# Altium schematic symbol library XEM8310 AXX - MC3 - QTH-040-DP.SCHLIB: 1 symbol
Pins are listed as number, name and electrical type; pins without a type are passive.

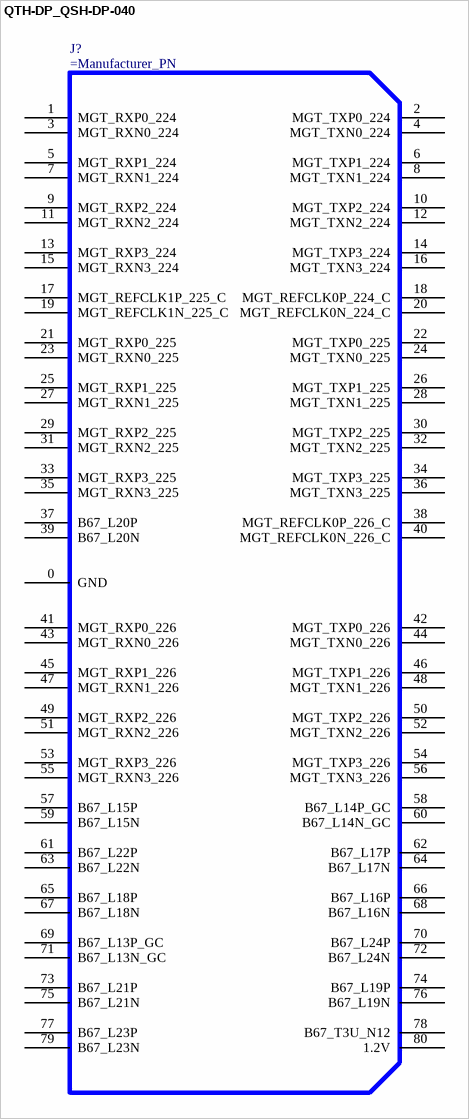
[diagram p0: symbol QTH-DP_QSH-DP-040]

## QTH-DP_QSH-DP-040
designator J?
0.5mm Double Row High Speed Socket Assembly
pins: 0 GND, 1 MGT_RXP0_224, 2 MGT_TXP0_224, 3 MGT_RXN0_224, 4 MGT_TXN0_224, 5 MGT_RXP1_224, 6 MGT_TXP1_224, 7 MGT_RXN1_224, 8 MGT_TXN1_224, 9 MGT_RXP2_224, 10 MGT_TXP2_224, 11 MGT_RXN2_224, 12 MGT_TXN2_224, 13 MGT_RXP3_224, 14 MGT_TXP3_224, 15 MGT_RXN3_224, 16 MGT_TXN3_224, 17 MGT_REFCLK1P_225_C, 18 MGT_REFCLK0P_224_C, 19 MGT_REFCLK1N_225_C, 20 MGT_REFCLK0N_224_C, 21 MGT_RXP0_225, 22 MGT_TXP0_225, 23 MGT_RXN0_225, 24 MGT_TXN0_225, 25 MGT_RXP1_225, 26 MGT_TXP1_225, 27 MGT_RXN1_225, 28 MGT_TXN1_225, 29 MGT_RXP2_225, 30 MGT_TXP2_225, 31 MGT_RXN2_225, 32 MGT_TXN2_225, 33 MGT_RXP3_225, 34 MGT_TXP3_225, 35 MGT_RXN3_225, 36 MGT_TXN3_225, 37 B67_L20P, 38 MGT_REFCLK0P_226_C, 39 B67_L20N, 40 MGT_REFCLK0N_226_C, 41 MGT_RXP0_226, 42 MGT_TXP0_226, 43 MGT_RXN0_226, 44 MGT_TXN0_226, 45 MGT_RXP1_226, 46 MGT_TXP1_226, 47 MGT_RXN1_226, 48 MGT_TXN1_226, 49 MGT_RXP2_226, 50 MGT_TXP2_226, 51 MGT_RXN2_226, 52 MGT_TXN2_226, 53 MGT_RXP3_226, 54 MGT_TXP3_226, 55 MGT_RXN3_226, 56 MGT_TXN3_226, 57 B67_L15P, 58 B67_L14P_GC, 59 B67_L15N, 60 B67_L14N_GC, 61 B67_L22P, 62 B67_L17P, 63 B67_L22N, 64 B67_L17N, 65 B67_L18P, 66 B67_L16P, 67 B67_L18N, 68 B67_L16N, 69 B67_L13P_GC, 70 B67_L24P, 71 B67_L13N_GC, 72 B67_L24N, 73 B67_L21P, 74 B67_L19P, 75 B67_L21N, 76 B67_L19N, 77 B67_L23P, 78 B67_T3U_N12, 79 B67_L23N, 80 1.2V
1 alternate drawing of the same symbol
